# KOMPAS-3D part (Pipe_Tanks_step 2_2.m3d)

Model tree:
1. X Axis
2. Y Axis
3. Z Axis  (labels: Pipe Dn 50; T-Bend Dn 50)
     Òîëùèíà ñòåíêè 1 = 1

Referenced files in C:\Documents and Settings\kashirsky\Мои документы\Camtasia Studio\Pipelines3D\Tanks\: Tanks_step 2.a3d
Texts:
  Pipe Dn 50
  Steel ASTM A295
  Three Point Plane
  Plane at Angle
  Line and Point Plane
  Axis through Two Vertices
  Axis of Feature
  Axis of Conical Surface
  Axis through Edge
  Trim by Surface
  Trim by Sketch
  Feature with No History
  Intersection Axis of Two Planes
  Two Line Plane
  Line and Face Plane
  Bend by line
  Hole in sheet body
  Cut in sheet body
  Point in CM
  Linear Dimension from Line to Point
  Surface Finish Symbol
  Geometric Tolerance Symbol
  Leader #1
  Leader #2
  Leader #3
  Shape Deviations and Datum
  Node point number
  Mark of coordination axis
  Node point designation
  Mark/Reference designation with leader
  Mark/reference designation on line
  Mark/Reference designation without leader
  T-Bend Dn 50
  Plane of section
